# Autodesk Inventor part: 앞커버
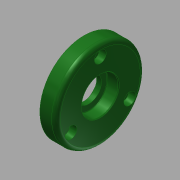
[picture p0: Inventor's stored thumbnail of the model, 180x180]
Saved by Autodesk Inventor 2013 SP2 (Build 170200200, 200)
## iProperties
Created: 2015-11
Part Number: 앞커버
Material: 알루미늄 6061
Document SubType Name: Modeling
Designer: mduedu
Density: 1 g/cm^3
Author: mduedu
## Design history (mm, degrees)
sketch "스케치5"
  geometry: C1 r 30 at (0, 0); 2 further points
  constraints: 2 coincident, 1 centre point
  dimensions: "d66" = 60 diameter of C1
extrude "돌출2" new body sketch "스케치5" distance "d67" = 8; taper "d68" = 0 deg
sketch "스케치9"
  geometry: C1 r 16.5 at (0, 0); 1 further point
  constraints: 1 centre point, 1 coincident
  dimensions: "d146" = 33 diameter of C1
extrude "돌출4" join sketch "스케치9" distance "d147" = 4; taper "d148" = -30 deg
sketch "스케치6"
  geometry: C1 r 16 at (0, 0); 1 further point
  constraints: 1 centre point, 1 coincident
  dimensions: "d69" = 32 diameter of C1
extrude "돌출3" join sketch "스케치6" distance "d70" = 3; taper "d71" = 0 deg
hole "구멍7" diameter "d98" = 25; stored, may be unused: countersink angle "d102" = 90 deg, drill point angle "d104" = 0 deg; dims "d96" = 10, "d97" = 10, "d99" = 6, "d100" = 4, "d101" = 2, "d103" = 3
hole "구멍8" diameter "d107" = 25; stored, may be unused: countersink angle "d111" = 90 deg, drill point angle "d113" = 0 deg; dims "d108" = 6, "d109" = 4, "d110" = 2, "d112" = 7.3, "d151" = 10, "d152" = 10
hole "구멍9" diameter "d116" = 18; stored, may be unused: countersink angle "d120" = 90 deg, drill point angle "d122" = 0 deg; dims "d117" = 6, "d118" = 4, "d119" = 2, "d121" = 7.7, "d154" = 10, "d155" = 10
chamfer "모따기2" distance "d123" = 0.6; stored, may be unused: second distance "d124" = 2, angle "d125" = 30 deg
fillet "모깎기11" dims "d126" = 0.3
fillet "모깎기13" dims "d128" = 3
fillet "모깎기14" dims "d129" = 3
fillet "모깎기15" dims "d130" = 0.3
sketch "스케치8" dims "d131" = 46
  geometry: 3 further points
  constraints: 2 vertical alignment, 1 coincident, 2 other
hole "구멍10" sketch "스케치8" at (0, 23) diameter "d132" = 4.5; stored, may be unused: countersink angle "d136" = 90 deg, drill point angle "d138" = 0 deg; dims "d133" = 6, "d134" = 8, "d135" = 4.6, "d137" = 7.7
chamfer "모따기3" distance "d143" = 1; stored, may be unused: second distance "d144" = 2, angle "d145" = 45 deg
fillet "모깎기16" dims "d149" = 1
node "솔리드2"
pattern_circular "원형 패턴4" dims angle "d140" = 360 deg
